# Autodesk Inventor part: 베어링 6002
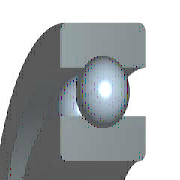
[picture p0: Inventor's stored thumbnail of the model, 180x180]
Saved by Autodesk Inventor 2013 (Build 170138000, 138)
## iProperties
IsCustomPart: 0
Created: 2012-02
Part Number: 베어링 6002
Material: 강철, 연강
Description: 깊은 그루브 볼 베어링
Document SubType Name: Modeling
Standard: KS B 2023
Designer: mduedu
Standards Organization: KS
Language: ko-KR
Size Designation: 6002 - 15 x 32 x 9
Categories: <MemberInstance><Categories><Category DisplayName="샤프트 부품" InternalName="7f7aeb1f-a693-4053-b835-cee3144e0d98" Mnemonic="SHFT"><Category DisplayName="베어링" Inter
Density: 1 g/cm^3
Author: mduedu
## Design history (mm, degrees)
sketch "스케치" dims "d0" = 4.42 (= -0.26 x WD + 0.26 x BD)
  geometry: L1 (2.29, 11.75)-(6.71, 11.75); L2 (4.5, 11.75)-(4.5, 9.54); L3 (4.5, 11.75)-(4.5, 13.96); L4 (2.858, 10.271)-(0, 10.271); L5 (0, 7.5)-(9, 7.5); L6 (2.858, 13.229)-(0, 13.229); L7 (0, 16)-(9, 16); L8 (9, 7.5)-(9, 10.271); L9 (6.142, 10.271)-(9, 10.271); L10 (6.142, 13.229)-(9, 13.229); L11 (9, 16)-(9, 13.229); L12 (-1.4, 0)-(8.4, 0) reference; L13 (0, -0.3)-(0, 5.3) reference
  constraints: 22 end point, 4 point on line, 2 collinear, 2 perpendicular, 2 symmetric about line, 1 midpoint, 1 parallel, 14 other
  dimensions: "d9" = 15 diameter of L5 L12 (= WD); "d11" = 32 diameter of L7 L12 (= BD); "d12" = 9 distance between parallel lines of L8 L13 (= KB); "d13" = 20.542 diameter of L9 L12 (= 0.326 x BD + 0.674 x WD)
revolve "본체" stored, may be unused: angle "d6" = 90 deg
revolve "볼" stored, may be unused: angle "d7" = 90 deg
pattern_circular "IDS_ARRAYBALL[SIMPL:T]" dims angle "d3" = 360 deg
body "Solid1"
fillet "모깎기1" dims "d1" = 0.3 (= KRS)
other parameters: "WD" = 15 [user parameter; used in 5 equation terms], "BD" = 32 [user parameter; used in 5 equation terms], "KB" = 9 [user parameter; used in 1 equation term], "KRS" = 0.3 [user parameter; used in 1 equation term], "d4" = 0, "d5" = 0, "d8" = 0, "d14" = 0, "d15" = 0, "BBA" = 0 [user parameter], "BC0" = 2850000 [user parameter], "BC" = 5590000 [user parameter], "BR" = 16 (= 0.5 x BD) [user parameter], "WR" = 7.5 (= 0.5 x WD) [user parameter]
